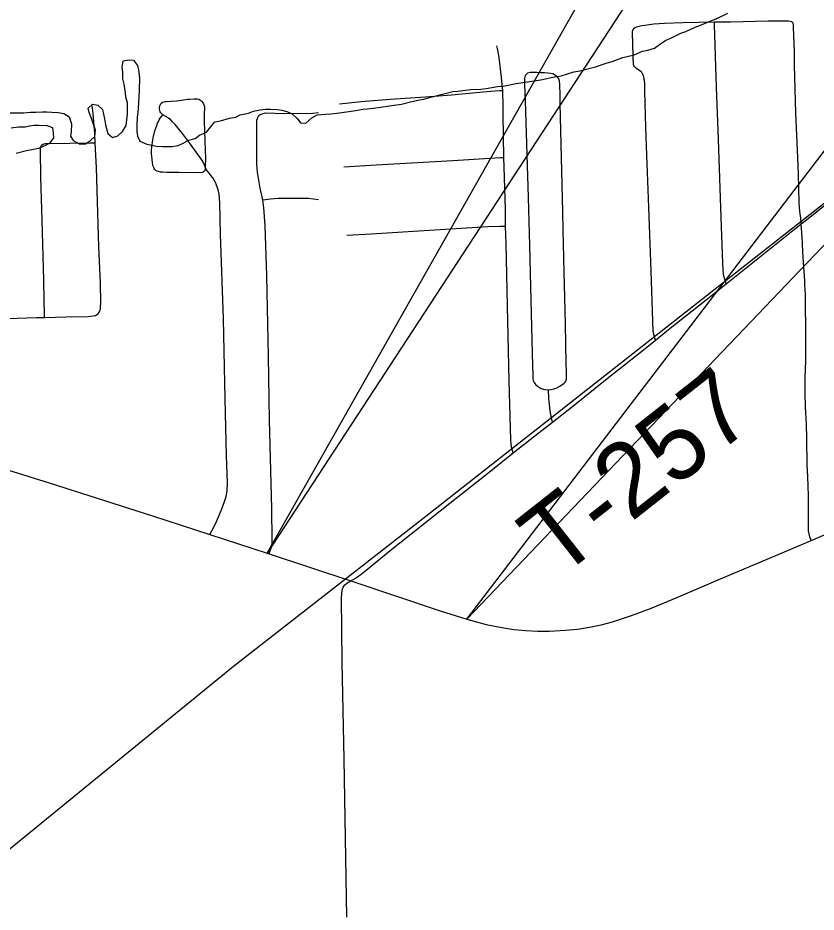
# Model space of a CAD drawing. Extents: x -12 to 34, y 0 to 22.
# Drawn here: x 4.871 to 5.489, y 17.363 to 18.055 of the extents above; entities that cross this region are included whole.
import ezdxf

# ---------------------------------------------------------------- set-up
doc = ezdxf.new("R2010")
doc.units = 0
for name, color, linetype in [('GM_X_Adjacent_County', 7, 'Continuous'), ('GM_X_Corporation', 7, 'Continuous'), ('GM_X_County_Road_Text', 7, 'Continuous'), ('GM_X_Major_Lake', 7, 'Continuous'), ('GM_X_Major_River', 7, 'Continuous'), ('GM_X_Minor_Lake', 7, 'Continuous'), ('GM_X_Township', 7, 'Continuous')]:
    doc.layers.add(name, color=color, linetype=linetype)

msp = doc.modelspace()

# ---------------------------------------------------------------- linework, layer by layer
at = {"layer": 'GM_X_Adjacent_County'}
for points in [[(6.62656, 20.0306), (5.06408, 17.64098), (6.62656, 20.40004)], [(6.62656, 19.06353), (5.2189, 17.58992), (6.62656, 19.43297)]]:
    msp.add_lwpolyline(points, close=True, dxfattribs=at)
for points in [[(6.62656, 20.0306), (5.06408, 17.64098), (6.62656, 20.40004)], [(6.62656, 19.06353), (5.2189, 17.58992), (6.62656, 19.43297)]]:
    msp.add_lwpolyline(points, dxfattribs=at)
at = {"layer": 'GM_X_Corporation'}
msp.add_lwpolyline([(4.21516, 16.89608), (4.31222, 16.96474), (4.74688, 17.31604), (5.03809, 17.55354), (5.18709, 17.66982), (5.65945, 18.04091), (6.05453, 18.35511), (6.09781, 18.38665), (6.1312, 18.40211), (6.16953, 18.40953), (6.55349, 18.44232), (6.69012, 18.44788), (6.85026, 18.4485), (6.9294, 18.45221), (7.10746, 18.45407), (7.25585, 18.4584), (7.28615, 18.45159), (7.37827, 18.44726), (7.7344, 18.45716)], dxfattribs=at)
at = {"layer": 'GM_X_Major_Lake'}
msp.add_lwpolyline([(4.85971, 17.70657), (4.89539, 17.69556), (4.9754, 17.67003), (5.01964, 17.65554), (5.06408, 17.64098), (5.06565, 17.64047), (5.12888, 17.6196), (5.19815, 17.59638), (5.2189, 17.58992), (5.23386, 17.58593), (5.24597, 17.58341), (5.25514, 17.58205), (5.26437, 17.58113), (5.27363, 17.58067), (5.2829, 17.58067), (5.29526, 17.58132), (5.30449, 17.58227), (5.31366, 17.58366), (5.32273, 17.5855), (5.33169, 17.5879), (5.34638, 17.59278), (5.36092, 17.59817), (5.381, 17.60644), (5.4153, 17.62107), (5.46962, 17.64408), (5.48538, 17.65081), (5.51247, 17.66238)], dxfattribs=at)
at = {"layer": 'GM_X_Major_River'}
msp.add_line((5.41972, 17.84962), (5.47765, 17.89598), dxfattribs=at)
for points in [[(5.36478, 17.80595), (5.36394, 17.80916), (5.36349, 17.81085), (5.3632, 17.81269), (5.36251, 17.82842), (5.36144, 17.85946), (5.35968, 17.9089), (5.35818, 17.9491), (5.35752, 17.97077), (5.35673, 17.99883), (5.35655, 18.00424), (5.35624, 18.00714), (5.35596, 18.00908), (5.35578, 18.00995), (5.35549, 18.01085), (5.3552, 18.01161), (5.35484, 18.01237), (5.3544, 18.01298), (5.35398, 18.01347), (5.35256, 18.01463), (5.35123, 18.0156), (5.35016, 18.0164), (5.34916, 18.01726), (5.34856, 18.01791), (5.34817, 18.01855), (5.34791, 18.01941), (5.34777, 18.02065), (5.34759, 18.02403), (5.3475, 18.0282), (5.34732, 18.03316), (5.34729, 18.03657), (5.34707, 18.04257), (5.34713, 18.04512), (5.34726, 18.04579), (5.34751, 18.0464), (5.34828, 18.04742), (5.34922, 18.04802), (5.35027, 18.04849)], [(5.35027, 18.04849), (5.35212, 18.049), (5.35429, 18.04951), (5.3567, 18.04991), (5.36001, 18.05036), (5.36366, 18.05074), (5.37176, 18.05131), (5.38607, 18.05195), (5.41058, 18.05229)], [(5.41058, 18.05229), (5.42304, 18.05246), (5.45224, 18.05318), (5.46113, 18.05323), (5.46583, 18.05318), (5.46787, 18.05318), (5.46915, 18.05302), (5.47031, 18.05257), (5.47108, 18.05191)], [(5.41972, 17.84962), (5.41888, 17.85237), (5.41817, 17.85468), (5.41763, 17.85734), (5.41728, 17.86053), (5.41694, 17.86575), (5.41599, 17.89375), (5.41376, 17.9612), (5.4122, 18.00193), (5.41065, 18.05008), (5.41058, 18.05229)], [(5.47765, 17.89598), (5.47735, 17.90074), (5.47701, 17.90351), (5.47666, 17.9062), (5.47639, 17.90876), (5.47625, 17.91276), (5.47562, 17.93445), (5.47507, 17.94723), (5.47361, 17.98183), (5.47264, 18.01885), (5.47242, 18.02964), (5.47169, 18.0481), (5.47163, 18.04987), (5.47141, 18.0513), (5.47108, 18.05191)], [(5.24658, 17.99932), (5.24622, 18.00392), (5.24569, 18.00923), (5.24374, 18.02467), (5.24304, 18.0292), (5.24251, 18.03168), (5.24189, 18.03372)], [(5.2934, 17.89146), (5.29306, 17.90528), (5.29107, 17.98923), (5.29099, 17.99763), (5.2909, 18.00178), (5.29074, 18.00419), (5.29048, 18.00636), (5.28991, 18.00835), (5.28915, 18.00943), (5.28824, 18.01035), (5.28674, 18.01143), (5.28525, 18.0121), (5.28375, 18.01243), (5.28159, 18.01268), (5.27888, 18.01289), (5.27599, 18.01305), (5.27302, 18.01317), (5.27011, 18.01317), (5.26789, 18.0132), (5.26672, 18.01294), (5.26586, 18.01259), (5.2649, 18.01193), (5.26419, 18.01122), (5.26371, 18.01018), (5.26354, 18.00843), (5.26354, 18.00627), (5.26354, 18.00386), (5.26396, 17.99113), (5.26636, 17.91649), (5.26724, 17.87921), (5.26871, 17.82638), (5.26973, 17.78596), (5.2698, 17.77972), (5.26997, 17.77632), (5.27022, 17.77482), (5.2708, 17.77324), (5.27138, 17.77232), (5.27213, 17.77133), (5.27338, 17.77025), (5.27496, 17.76925), (5.27646, 17.76858), (5.27912, 17.76784), (5.28203, 17.7675)], [(5.12013, 17.98896), (5.13698, 17.99065), (5.15928, 17.99253), (5.18685, 17.99441), (5.20694, 17.99594), (5.23706, 17.99867), (5.24404, 17.99918), (5.24658, 17.99932)], [(5.24738, 17.94743), (5.24702, 17.98085), (5.24687, 17.9905), (5.24666, 17.99552), (5.24658, 17.99932)], [(4.9309, 17.95867), (4.9306, 17.96574), (4.92949, 17.98135), (4.92873, 17.98756)], [(4.98338, 17.98053), (4.98247, 17.98125), (4.98178, 17.98192), (4.98128, 17.98269), (4.98094, 17.98366), (4.98074, 17.9848), (4.98078, 17.98603), (4.98105, 17.9873), (4.98153, 17.98846), (4.98218, 17.98945), (4.98271, 17.98993), (4.98331, 17.99029), (4.98503, 17.99067), (4.98627, 17.9908), (4.98978, 17.991), (4.99425, 17.99134), (4.9979, 17.99185), (5.00078, 17.99228), (5.00267, 17.9925), (5.00396, 17.99263), (5.00743, 17.99279), (5.00854, 17.99279), (5.00983, 17.99269), (5.01118, 17.99243), (5.01196, 17.99206), (5.01276, 17.99156), (5.01358, 17.99073), (5.01441, 17.98961), (5.01484, 17.98889), (5.01518, 17.98807), (5.0155, 17.98676), (5.01558, 17.98493), (5.01548, 17.98164), (5.01545, 17.9754), (5.01599, 17.95993), (5.01629, 17.94662), (5.01609, 17.94003)], [(5.01609, 17.94003), (5.01609, 17.93832), (5.01597, 17.93763), (5.01569, 17.93692), (5.01489, 17.93622), (5.01369, 17.93572), (5.01116, 17.93556), (4.99575, 17.93567), (4.98635, 17.93574), (4.98327, 17.93593), (4.98154, 17.93611), (4.97999, 17.93642), (4.97892, 17.93679), (4.97798, 17.93742), (4.97726, 17.9381), (4.97669, 17.93892), (4.97634, 17.93968), (4.97598, 17.94072), (4.97569, 17.94182), (4.97544, 17.94324), (4.975, 17.94618), (4.97478, 17.94817), (4.9746, 17.95057), (4.97468, 17.95292), (4.9749, 17.95582), (4.97528, 17.95892), (4.97588, 17.96252), (4.97718, 17.96802), (4.97784, 17.97017), (4.97858, 17.97222), (4.97934, 17.97408), (4.97991, 17.97527), (4.98063, 17.97653), (4.98133, 17.97773), (4.98338, 17.98053)], [(5.01609, 17.94003), (5.01508, 17.94267), (5.01392, 17.94495), (5.01289, 17.94652), (5.00408, 17.95862), (4.99848, 17.96602), (4.99288, 17.97292), (4.99093, 17.97508), (4.98927, 17.97667), (4.98788, 17.97762), (4.98568, 17.97912), (4.98338, 17.98053)], [(5.06084, 17.91454), (5.05882, 17.92362), (5.05757, 17.9298), (5.05666, 17.93597), (5.05612, 17.94232), (5.05612, 17.95157), (5.05623, 17.97475), (5.05627, 17.97629), (5.05659, 17.97766), (5.0574, 17.97956)], [(5.0574, 17.97956), (5.05863, 17.98056), (5.05981, 17.98105), (5.06099, 17.98146), (5.06273, 17.98183), (5.07008, 17.98169), (5.09348, 17.98133), (5.09951, 17.98175), (5.10383, 17.98224)], [(4.89002, 17.95716), (4.89127, 17.95783), (4.89254, 17.95813), (4.89389, 17.9583), (4.89541, 17.95834), (4.92729, 17.95863), (4.9309, 17.95867)], [(4.93326, 17.82653), (4.93405, 17.82753), (4.93449, 17.82849), (4.93475, 17.82938), (4.93497, 17.83032), (4.93517, 17.83229), (4.93522, 17.83457), (4.93501, 17.85024), (4.93385, 17.87832), (4.93206, 17.93935), (4.9309, 17.95867)], [(4.89179, 17.82361), (4.89174, 17.82592), (4.89155, 17.83705), (4.89115, 17.85234), (4.88995, 17.89883), (4.88876, 17.9318), (4.8885, 17.953), (4.8886, 17.95426), (4.88889, 17.95532), (4.8892, 17.95613), (4.89002, 17.95716)], [(5.12349, 17.94014), (5.14848, 17.94158), (5.20784, 17.94516), (5.24473, 17.94726), (5.24738, 17.94743)], [(5.2488, 17.89429), (5.24865, 17.90727), (5.24765, 17.93991), (5.24738, 17.94743)], [(5.01964, 17.65554), (5.02151, 17.65894), (5.02395, 17.66337), (5.02672, 17.6698), (5.02949, 17.67656), (5.03137, 17.68177), (5.03237, 17.68488), (5.03314, 17.68898), (5.03347, 17.69552), (5.0327, 17.71646), (5.0317, 17.76057), (5.03025, 17.82242), (5.02813, 17.88814), (5.02751, 17.91219), (5.02723, 17.91566), (5.02695, 17.91898), (5.02612, 17.92245), (5.02539, 17.92472), (5.02409, 17.92792), (5.02314, 17.92982), (5.02196, 17.93172), (5.0209, 17.93313), (5.01911, 17.9353), (5.01727, 17.93791), (5.01609, 17.94003)], [(5.06084, 17.91454), (5.06664, 17.91529), (5.07244, 17.91583), (5.08424, 17.91584), (5.09222, 17.91596), (5.09621, 17.91584), (5.10402, 17.91493)], [(5.06565, 17.64047), (5.06631, 17.64222), (5.06732, 17.64492), (5.06778, 17.64702), (5.06795, 17.64871), (5.06805, 17.65111), (5.06775, 17.67574), (5.06608, 17.744), (5.06513, 17.79365), (5.06383, 17.85571), (5.06247, 17.89478), (5.06165, 17.9084), (5.06084, 17.91454)], [(5.47765, 17.89598), (5.48073, 17.89842), (5.49987, 17.91358)], [(5.12595, 17.88736), (5.14464, 17.88839), (5.23491, 17.89396), (5.24426, 17.89418), (5.2488, 17.89429)], [(5.25477, 17.71866), (5.25393, 17.72124), (5.25334, 17.72345), (5.25298, 17.7258), (5.25281, 17.7287), (5.25155, 17.77441), (5.25022, 17.83258), (5.24916, 17.88088), (5.2488, 17.89429)], [(5.28203, 17.7675), (5.28386, 17.76775), (5.2861, 17.76825), (5.2885, 17.76915), (5.29076, 17.77022), (5.29265, 17.77156), (5.29396, 17.77252), (5.29485, 17.77341), (5.29546, 17.77433), (5.29575, 17.77507), (5.29588, 17.77589), (5.29606, 17.77771), (5.29606, 17.77995), (5.29598, 17.78227), (5.29582, 17.78755), (5.29516, 17.81866), (5.29419, 17.85887), (5.2934, 17.89146)], [(5.48538, 17.65081), (5.48452, 17.65367), (5.48384, 17.656), (5.48341, 17.65824), (5.48327, 17.66073), (5.48332, 17.66593), (5.4834, 17.67387), (5.48331, 17.68569), (5.48288, 17.70003), (5.48245, 17.70961), (5.48201, 17.72981), (5.48175, 17.74095), (5.48115, 17.75424), (5.48089, 17.76504), (5.4808, 17.776), (5.48114, 17.78394), (5.48141, 17.78964), (5.48132, 17.80725), (5.48097, 17.84101), (5.48088, 17.84524), (5.48062, 17.8487), (5.48045, 17.85206), (5.47963, 17.86614), (5.47908, 17.87457), (5.47853, 17.88589), (5.47832, 17.88817), (5.47811, 17.8901), (5.47791, 17.89176), (5.47765, 17.89598)], [(5.36478, 17.80595), (5.37629, 17.81523), (5.40545, 17.83821), (5.41972, 17.84962)], [(4.84722, 17.82165), (4.85516, 17.82251), (4.88542, 17.82349), (4.89179, 17.82361)], [(4.89179, 17.82361), (4.9086, 17.8239), (4.92552, 17.82434), (4.92946, 17.82468), (4.93108, 17.82514), (4.9321, 17.82558), (4.93326, 17.82653)], [(5.28505, 17.74257), (5.30079, 17.75496), (5.32753, 17.77631), (5.35424, 17.79744), (5.36478, 17.80595)], [(5.28505, 17.74257), (5.28444, 17.74572), (5.28395, 17.74829), (5.28344, 17.75137), (5.28278, 17.75611), (5.28236, 17.76069), (5.28203, 17.7675)], [(5.25477, 17.71866), (5.27148, 17.73189), (5.28505, 17.74257)], [(5.12888, 17.6196), (5.13182, 17.62124), (5.13416, 17.62263), (5.13696, 17.62474), (5.14081, 17.62791), (5.14483, 17.63132), (5.15935, 17.64307), (5.20559, 17.67984), (5.23733, 17.70486), (5.25477, 17.71866)], [(5.12591, 17.35933), (5.12366, 17.48158), (5.12223, 17.55703), (5.12179, 17.60654), (5.12187, 17.60966), (5.12231, 17.61251), (5.12309, 17.61467), (5.12412, 17.61622), (5.12594, 17.61778), (5.12888, 17.6196)]]:
    msp.add_lwpolyline(points, dxfattribs=at)
at = {"layer": 'GM_X_Minor_Lake'}
for points in [[(4.95234, 18.01352), (4.95194, 18.01732), (4.95267, 18.02227), (4.95723, 18.02305), (4.96064, 18.02268), (4.9637, 18.01852), (4.96448, 18.0151), (4.96527, 18.00902), (4.96494, 17.99914), (4.96461, 17.99001), (4.96425, 17.98507), (4.96353, 17.97822), (4.96318, 17.97252), (4.9632, 17.96758), (4.9636, 17.96378), (4.96552, 17.95999), (4.97084, 17.95773), (4.97845, 17.95625), (4.983, 17.95589), (4.99022, 17.95592), (4.99515, 17.9567), (4.99856, 17.95824), (5.00348, 17.96092), (5.00841, 17.96209), (5.01181, 17.96476), (5.01712, 17.96707), (5.02014, 17.97088), (5.02353, 17.97508), (5.02808, 17.97586), (5.03491, 17.97779), (5.03984, 17.97858), (5.04325, 17.98049), (5.0497, 17.98166), (5.05348, 17.9832), (5.05879, 17.98436), (5.06297, 17.98476), (5.06677, 17.98478), (5.07208, 17.98442), (5.0755, 17.98406), (5.0793, 17.98294), (5.08349, 17.98106), (5.0873, 17.97765), (5.08998, 17.97425), (5.09416, 17.97388), (5.09869, 17.97808), (5.10286, 17.98039), (5.10931, 17.9808), (5.11348, 17.98119), (5.11804, 17.9816), (5.12373, 17.98238), (5.13094, 17.98356), (5.13852, 17.98473), (5.14194, 17.98513), (5.14839, 17.98592), (5.1518, 17.98631), (5.15901, 17.98749), (5.16243, 17.98788), (5.16812, 17.98867), (5.17608, 17.99061), (5.18215, 17.99215), (5.18556, 17.99255), (5.19087, 17.99409), (5.19997, 17.99642), (5.20793, 17.99836), (5.21173, 17.99875), (5.22197, 17.99994), (5.22957, 18.00035), (5.23374, 18.00076), (5.24246, 18.00231), (5.24702, 18.00272), (5.25688, 18.00466), (5.27281, 18.00701), (5.27737, 18.00779), (5.28647, 18.00974), (5.29178, 18.01052), (5.30164, 18.01361), (5.30619, 18.01439), (5.31832, 18.01749), (5.32742, 18.02057), (5.33121, 18.02173), (5.33955, 18.02481), (5.34296, 18.02558), (5.34827, 18.02675), (5.35471, 18.02982), (5.35888, 18.0306), (5.36419, 18.03214), (5.36797, 18.03482), (5.37289, 18.03826), (5.37668, 18.0398), (5.38463, 18.04364), (5.38842, 18.0448), (5.39562, 18.04825), (5.39979, 18.04979), (5.40774, 18.05325), (5.41191, 18.05479), (5.421, 18.05901)], [(4.861, 17.98193), (4.8758, 17.982), (4.88074, 17.9824), (4.88491, 17.98242), (4.89023, 17.98283), (4.89364, 17.98285), (4.89744, 17.98248), (4.90238, 17.98212), (4.90656, 17.98138), (4.91075, 17.97874), (4.91267, 17.97343), (4.91233, 17.96735), (4.91196, 17.96392), (4.91388, 17.96051), (4.91845, 17.95787), (4.92338, 17.95789), (4.92717, 17.96019), (4.93057, 17.96363), (4.9313, 17.96857), (4.92822, 17.97768), (4.9263, 17.98223), (4.92552, 17.98565), (4.92892, 17.98871), (4.9331, 17.98797), (4.93654, 17.98456), (4.93809, 17.97735), (4.93888, 17.97279), (4.94081, 17.96596), (4.94424, 17.96293), (4.94841, 17.96409), (4.95219, 17.96753), (4.95483, 17.9721), (4.95592, 17.98123), (4.95588, 17.98959), (4.95471, 17.99415), (4.95432, 17.99757), (4.95352, 18.00403), (4.95237, 18.0082), (4.95234, 18.01352)], [(4.86989, 17.9508), (4.87785, 17.95274), (4.88733, 17.95469), (4.89263, 17.95699), (4.89642, 17.95891), (4.89906, 17.96272), (4.89866, 17.96614), (4.89826, 17.97032), (4.8937, 17.97182), (4.88762, 17.97217), (4.88383, 17.97216), (4.88003, 17.97176), (4.87662, 17.97098), (4.87168, 17.97096), (4.86599, 17.97017)]]:
    msp.add_lwpolyline(points, dxfattribs=at)
at = {"layer": 'GM_X_Township'}
for points in [[(4.85971, 17.70657), (4.89539, 17.69556), (4.9754, 17.67003), (5.01964, 17.65554), (5.06408, 17.64098), (5.06565, 17.64047)], [(5.21979, 17.58968), (5.23386, 17.58593), (5.24597, 17.58341), (5.25514, 17.58205), (5.26437, 17.58113), (5.27363, 17.58067), (5.2829, 17.58067), (5.29526, 17.58132), (5.30449, 17.58227), (5.31366, 17.58366), (5.32273, 17.5855), (5.33169, 17.5879), (5.34638, 17.59278), (5.36092, 17.59817), (5.381, 17.60644), (5.4153, 17.62107), (5.46962, 17.64408), (5.48538, 17.65081), (5.51247, 17.66238)]]:
    msp.add_lwpolyline(points, dxfattribs=at)

# ---------------------------------------------------------------- texts
at = {"layer": 'GM_X_County_Road_Text'}
msp.add_text('T-257', height=0.056818, rotation=38.2672, dxfattribs=at).set_placement((5.28955, 17.62023))

doc.saveas('drawing.dxf')
